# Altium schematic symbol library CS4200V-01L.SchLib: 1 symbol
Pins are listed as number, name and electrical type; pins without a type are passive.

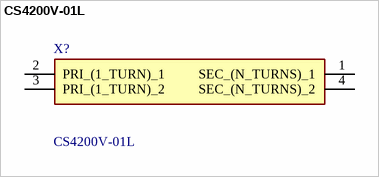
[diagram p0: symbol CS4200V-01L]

## CS4200V-01L
designator X?
TRANSFORMER, CURRENT SENSE, 1:200, 35A; Manufacturer_Name: COILCRAFT; Geometry.Height: 19.05mm
footprint CS4200V01L
pins: 1 SEC_(N_TURNS)_1, 2 PRI_(1_TURN)_1, 3 PRI_(1_TURN)_2, 4 SEC_(N_TURNS)_2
